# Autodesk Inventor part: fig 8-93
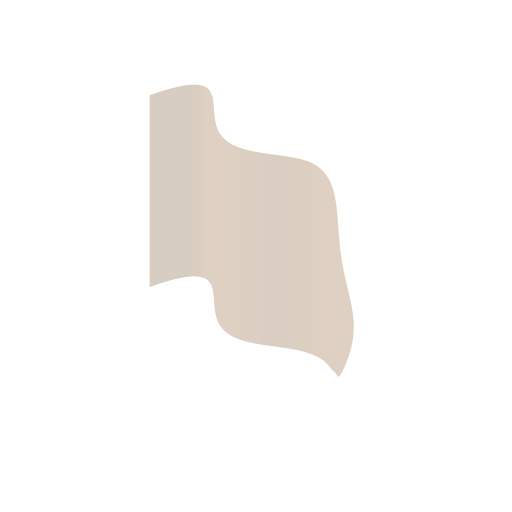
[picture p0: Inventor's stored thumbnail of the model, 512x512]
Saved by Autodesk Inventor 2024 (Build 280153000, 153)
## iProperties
Shininess: 64.0
Length Units: 11269
Angle Units: 11279
Time Units: 11290
Mass Units: 11283
Length Display Precision: 3
Angle Display Precision: 2
Compacted: True
Part Number: fig 8-93
Document SubType Name: Modeling
Created: 2003-08
Designer: Owner
Manufacturer: Standard
Standards Organization: Custom
Density: 1 g/cm^3
Material: Generic
Appearance: Default
Density: 0.0
Volumn: 0.0
Area: 0.0
PropertySet Name: Model Information
Control State: 0
Master: False
Checked Out: False
Author: Owner
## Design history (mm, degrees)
sketch "Sketch1"
  geometry: 7 further points
  constraints: 7 other
  dimensions: "d0" = 80 horizontal distance of point (40, 1.742) point (-40, -4.065); "d1" = 40 horizontal distance of point (0, 0) point (-40, -4.065)
extrude_surface "ExtrusionSrf1" sketch "Sketch1" dims "d2" = 80, "d3" = 0
sketch "Sketch2"
  geometry: L1 (40, 0)-(40, -40) reference; L2 (-40, 0)-(-40, -40) reference; 7 further points
  constraints: 2 point on line, 7 other
extrude_surface "ExtrusionSrf2" sketch "Sketch2" dims "d4" = 80, "d5" = 0
workplane "Work Plane1"
sketch "Sketch4"
  geometry: L1 (70.027, 16.004)-(-4, 16.004); A1 r 29.004 centre (-4, -13) between (-4, 16.004) and (-2.981, -41.986)
  constraints: 2 end point, 2 point on circle, 1 centre point, 1 horizontal, 1 tangent
feature "Trim1" sketch "Sketch4"
body "Srf1"
body "Srf2"
other parameters: "d6" = -54.75
